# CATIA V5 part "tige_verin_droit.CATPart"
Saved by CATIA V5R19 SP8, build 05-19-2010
Part number: tige_verin_droit
Publications: "Esquisse.3"
Material "Aluminium": density 2710 kg/m3, Young's modulus 7e+10 Pa, Poisson ratio 0.346, thermal expansion 2.36e-05 1/K
Bounding box of the stored display mesh (mm): x 615 to 735, y -48 to 48, z -248 to 812.5
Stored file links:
  G:\EU_thinkMotion\CFAO_2010\MMS_groupe2\MMS_groupe2\OK\mmartini\mmartiniCFAO\tige_verin_droit.CATPart
  C:\Users\Mathieu Martini\Desktop\CFAO\Animation\CFAO.CATProduct
  G:\EU_thinkMotion\CFAO_2010\MMS_groupe2\MMS_groupe2\OK\mmartini\mmartiniCFAO\Squelette.CATPart
  C:\Program Files\Dassault Systemes\B19\intel_a\startup\materials\French\Catalog.CATMaterial
  G:\EU_thinkMotion\CFAO_2010\MMS_groupe2\MMS_groupe2\OK\mmartini\mmartiniCFAO\Berceau.CATPart
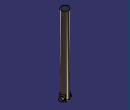
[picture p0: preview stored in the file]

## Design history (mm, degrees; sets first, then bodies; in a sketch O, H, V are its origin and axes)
External parameters (linked from other documents)
  External.diametre_canon = 150 mm
  External.diametre_verin = 120 mm
AxisSystem1: origin (0, 0, 0), X (1, 0, 0), Y (0, 1, 0), Z (0, 0, 1)
Set1
  Sketch1 on Plane1, origin (675, 0, 0), H (0, 1, 0), V (0, 0, 1)
    point P1 (0, -200)
    line L1 (48, -200) -> (48, 812.5)
    line L2 (48, 812.5) -> (0, 812.5)
    line L3 (0, 812.5) -> (0, -200)
    arc A1 centre (0, -200) radius 48 from (0, -248) to (48, -200) ccw
    line L4 (0, -200) -> (0, -248)
    reference projected point E1 (0, -200) from Point1
    length L3 = 1012.5 {= External.diametre_canon *6.75}
    radius A1 = 48 {= (External.diametre_verin -External.diametre_verin /5)/2}
    horizontal: L2 H
    vertical: L1 V, L3 V, L4 V
    tangency: A1 L1
    coincidence: P1 E1
Set2
  Plane1 "Plan_verin_droit": linked copy from another document
  Point1 "Point_verin_droit": linked copy from another document
  Plane2 "Plan_rayon_ext_verin_droit": linked copy from another document
  Plane3 "Plan_rayon_int_verin_droit": linked copy from another document
Body1 (main body)
  Shaft1: profile Sketch1, axis Sketch1.L3, angle 360
  Sketch2 on Plane1, origin (675, 0, 0), H (0, 1, 0), V (0, 0, 1)
    circle A1 centre (0, -200) radius 24
    point P1 (0, -200)
    reference projected point E1 (0, -200) from Point1
    radius A1 = 24 {= External.diametre_verin /5}
    coincidence: P1 E1
  Pad1: profile Sketch2, direction (1, 0, 0), up to Plane2, opposite side up to Plane3
  Sketch3 on Plane2, origin (735, 0, 0), H (0, 1, 0), V (0, 0, 1)
    circle A1 centre (0, -200) radius 24
    point P1 (0, -200)
    reference projected point E1 (0, -200) from Point1
    line L1 (-60, -140) -> (60, -140)
    line L2 (60, -140) -> (60, -260)
    line L3 (60, -260) -> (-60, -260)
    line L4 (-60, -260) -> (-60, -140)
    radius A1 = 24 {= External.diametre_verin /5}
    length L1 = 120 {= External.diametre_verin}
    length L4 = 120 {= External.diametre_verin}
    distance L1 P1 = 60 {= External.diametre_verin /2}
    distance P1 L2 = 60 {= External.diametre_verin /2}
    coincidence: P1 E1
    horizontal: L1 H, L3 H
    vertical: L2 V, L4 V
  Pocket1: profile Sketch3, direction (-1, 0, 0), length 30 {= External.diametre_verin /4}
  Sketch4 on start face of Pad1, origin (615, 0, 0), H (0, -1, 0), V (0, 0, 1)
    circle A1 centre (0, -200) radius 24
    point P1 (0, -200)
    reference projected point E1 (0, -200) from Point1
    line L1 (-60, -140) -> (60, -140)
    line L2 (60, -140) -> (60, -260)
    line L3 (60, -260) -> (-60, -260)
    line L4 (-60, -260) -> (-60, -140)
    radius A1 = 24 {= External.diametre_verin /5}
    distance P1 L2 = 60 {= External.diametre_verin /2}
    length L1 = 120 {= External.diametre_verin}
    distance L1 P1 = 60 {= External.diametre_verin /2}
    length L4 = 120 {= External.diametre_verin}
    coincidence: P1 E1
    horizontal: L1 H, L3 H
    vertical: L2 V, L4 V
  Pocket2: profile Sketch4, direction (1, 0, 0), length 30 {= External.diametre_verin /4}
Relations
  Pad1.FirstLimit.Length = External.diametre_verin *0.75 (deactivated)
